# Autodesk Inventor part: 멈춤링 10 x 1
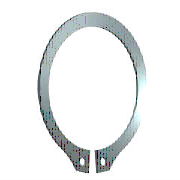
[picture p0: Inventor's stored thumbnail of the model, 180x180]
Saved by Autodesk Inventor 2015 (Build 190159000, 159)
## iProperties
IsCustomPart: 0
Created: 2009-02
Part Number: 멈춤링 10 x 1
Material: Steel, Mild
Description: 리테이닝 링(C형)
Document SubType Name: Modeling
Standard: KS B 1336
Designer: SeoGD™
Standards Organization: KS
Language: ko-KR
Size Designation: 10 x 1
Categories: <MemberInstance><Categories><Category DisplayName="샤프트 부품" InternalName="7f7aeb1f-a693-4053-b835-cee3144e0d98" Mnemonic="SHFT"><Category DisplayName="써클립" Inter
Density: 7.86 g/cm^3
Appearance: Metal-Steel
Mass: 0.423087 g
Surface Area: 1.9243 cm^2
Volume: 0.0538279 cm^3
Author: SeoGD™
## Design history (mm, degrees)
sketch "스케치1"
  geometry: L1 (-6, 0)-(6, 0) reference; L2 (0, 20.189)-(0, -80.536) reference; L3 (-48.09, 0)-(48.09, 0) reference; L4 (-0.3, -9.791)-(-0.3, -12.791); L5 (-0.3, -6.54)-(-0.3, -13.29); L6 (-2.795, 1.6)-(3.672, 1.6); L7 (0.3, -6.54)-(0.3, -13.29); L8 (0.3, -9.791)-(0.3, -12.791); C1 r 0.6 at (-1.2, -11.486); C2 r 0.6 at (1.2, -11.486); A1 r 4.8 centre (0, -5) between (0.3, -9.791) and (-0.3, -9.791); A2 r 6.2 centre (0, -4.6) between (2.988, -10.033) and (-2.988, -10.033); A3 r 7.796 centre (0, -5) between (-1.418, -12.666) and (-0.3, -12.791); A4 r 1.2 centre (-1.2, -11.486) between (-2.383, -11.285) and (-1.418, -12.666); A5 r 1.2 centre (-3.566, -11.084) between (-2.383, -11.285) and (-2.988, -10.033); A6 r 1.2 centre (3.566, -11.084) between (2.988, -10.033) and (2.383, -11.285); A7 r 1.2 centre (1.2, -11.486) between (1.418, -12.666) and (2.383, -11.285); A8 r 7.796 centre (0, -5) between (0.3, -12.791) and (1.418, -12.666)
  constraints: 16 point on circle, 12 end point, 10 centre point, 9 symmetric about line, 5 point on line, 4 tangent, 3 coincident, 2 horizontal, 1 perpendicular, 1 vertical, 5 other
  dimensions: "d0" = 9.6 diameter of A1 (= ND); "d1" = 3 distance of L4.end L4.start (= SRB2); "d6" = 0.3 distance between parallel lines of L2 L5 (= 0.25 x SD5); "d7" = 1.6 distance between parallel lines of L6 L3 (= SRB1); "d8" = 0.4 distance of A1.centre A2.centre (= 0.25 x SRB1); "d9" = 1.2 radius of A4 (= SD5); "d10" = 1.2 radius of A5 (= SD5); "d11" = 0.9 distance from line of L4 A4.centre (= 0.75 x SD5); "d12" = 1.2 diameter of C1 (= SD5); "d13" = 1.2 diameter of C2 (= SD5); "d14" = 5 distance from line of A1.centre L1 (= 0.5 x WD)
extrude "본체" new body sketch "스케치1" distance "d2" = 1 (= SD); taper "d3" = 0 deg
workaxis "Work Axis1"
workplane "Work Plane1"
body "Solid1"
other parameters: "SD" = 1 [user parameter; used in 1 equation term], "SRB1" = 1.6 [user parameter; used in 2 equation terms], "ND" = 9.6 [user parameter; used in 1 equation term], "SRB2" = 3 [user parameter; used in 1 equation term], "SD5" = 1.2 [user parameter; used in 6 equation terms], "d15" = 0, "d16" = 0, "d17" = 0, "d41" = 0, "d42" = 0, "SD3" = 9.3 [user parameter], "WDMAX" = 11 [user parameter]
